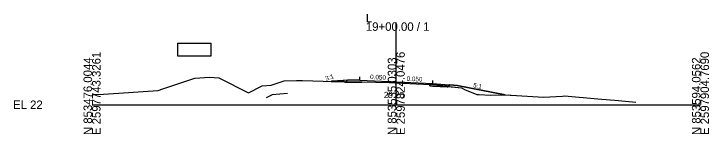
# Model space of a CAD drawing. Extents: x -26 to 1203, y -10 to 9526.
# Drawn here: x -25.7 to 202.8, y 8990.3 to 9030 of the extents above; entities that cross this region are included whole.
import ezdxf

# ---------------------------------------------------------------- set-up
doc = ezdxf.new("R2010")
doc.units = 0
for name, color, linetype in [('Default', 7, 'Continuous'), ('Exist Cross Section Cell', 7, 'Continuous'), ('Exist XS Center Line Elevation Label', 7, 'Continuous'), ('Exist XS Ground Line', 7, 'Continuous'), ('Prop XS Earthwork Shape', 7, 'Continuous'), ('Prop XS EOT Tick Mark', 7, 'Continuous'), ('Prop XS Finish Grade', 7, 'Continuous'), ('Prop XS Finish Grade Earthwork', 7, 'Continuous'), ('Prop XS Finish Grade Paved Shoulder', 7, 'Continuous'), ('Prop XS Finish Grade Pavement', 7, 'Continuous'), ('Prop XS Pvmt Edge Slope', 7, 'Continuous'), ('Prop XS SE Text', 7, 'Continuous'), ('Prop XS Side Slope Text', 7, 'Continuous'), ('Prop XS Subgrade Earthwork', 7, 'Continuous')]:
    doc.layers.add(name, color=color, linetype=linetype)

msp = doc.modelspace()

# ---------------------------------------------------------------- linework, layer by layer
at = {"layer": 'Default'}
msp.add_line((64.2, 9003.68), (59.2, 9003.27), dxfattribs=at)
msp.add_lwpolyline([(28.25, 9020.35), (39.06, 9020.35), (39.06, 9016), (28.25, 9016)], close=True, dxfattribs=at)
msp.add_lwpolyline([(59.2, 9003.27), (57.2, 9002.27)], dxfattribs=at)
at = {"layer": 'Exist Cross Section Cell'}
for p, q in [((100, 9000), (100, 9027.17)), ((0, 9000), (100, 9000)), ((100, 9000), (200, 9000))]:
    msp.add_line(p, q, dxfattribs=at)
at = {"layer": 'Exist XS Ground Line'}
for p, q in [((33.74, 9008.75), (38.63, 9009.06)), ((38.63, 9009.06), (41.64, 9008.88)), ((41.64, 9008.88), (51.45, 9003.98)), ((23.28, 9005.23), (33.74, 9008.75)), ((58.91, 9006.46), (63.16, 9007.88)), ((63.16, 9007.88), (67.16, 9008)), ((67.16, 9008), (69.16, 9007.95)), ((69.16, 9007.95), (79.41, 9007.66)), ((79.41, 9007.66), (88.8, 9007.53)), ((88.8, 9007.53), (97.62, 9007.32)), ((97.62, 9007.32), (99.87, 9007.26)), ((99.87, 9007.26), (108.97, 9006.82)), ((108.97, 9006.82), (111.07, 9006.71)), ((111.07, 9006.71), (114.42, 9006.29)), ((3.76, 9003.53), (21.77, 9004.69)), ((21.77, 9004.69), (23.28, 9005.23)), ((51.45, 9003.98), (55.91, 9006.21)), ((55.91, 9006.21), (58.91, 9006.46)), ((114.42, 9006.29), (121.48, 9005.53)), ((121.48, 9005.53), (122.67, 9004.88)), ((122.67, 9004.88), (125.12, 9003.98)), ((0, 9003.35), (1.5, 9003.41)), ((1.5, 9003.41), (3.76, 9003.53)), ((125.12, 9003.98), (126.52, 9003.34)), ((126.52, 9003.34), (127.27, 9003.35)), ((127.27, 9003.35), (130.85, 9003.19)), ((130.85, 9003.19), (136.78, 9003.25)), ((136.78, 9003.25), (137.46, 9003.21)), ((137.46, 9003.21), (137.8, 9003.2)), ((137.8, 9003.2), (148.41, 9002.47)), ((148.41, 9002.47), (154.65, 9002.88)), ((154.65, 9002.88), (155.29, 9002.96)), ((155.29, 9002.96), (166.27, 9001.98)), ((166.27, 9001.98), (173.06, 9001.35)), ((173.06, 9001.35), (178.76, 9000.89))]:
    msp.add_line(p, q, dxfattribs=at)
at = {"layer": 'Prop XS Earthwork Shape'}
for points in [[(78.58, 9007.69), (79.41, 9007.66), (82.9, 9007.61), (82.51, 9008.01), (78.76, 9007.75)], [(83.2, 9007.31), (82.9, 9007.61), (88.73, 9007.53), (88.73, 9007.33), (88, 9007.36)], [(111.03, 9006.22), (112, 9006.16), (116.84, 9005.87), (116.98, 9006.01), (114.42, 9006.29), (111.07, 9006.71), (111.03, 9006.71)], [(126.52, 9003.34), (127.27, 9003.35), (130.85, 9003.19), (135.78, 9003.24), (120, 9006.39), (117.56, 9006.59), (116.98, 9006.01), (121.48, 9005.53), (122.67, 9004.88), (125.12, 9003.98)]]:
    msp.add_lwpolyline(points, close=True, dxfattribs=at)
at = {"layer": 'Prop XS EOT Tick Mark'}
for p, q in [((88, 9008.15), (88, 9009.15)), ((112, 9006.95), (112, 9007.95))]:
    msp.add_line(p, q, dxfattribs=at)
at = {"layer": 'Prop XS Finish Grade'}
for p, q in [((84, 9008.11), (82.51, 9008.01)), ((116, 9006.71), (117.56, 9006.59))]:
    msp.add_line(p, q, dxfattribs=at)
at = {"layer": 'Prop XS Finish Grade Earthwork'}
for p, q in [((78.76, 9007.75), (78.58, 9007.69)), ((82.51, 9008.01), (78.76, 9007.75)), ((117.56, 9006.59), (120, 9006.39)), ((120, 9006.39), (135.78, 9003.24))]:
    msp.add_line(p, q, dxfattribs=at)
at = {"layer": 'Prop XS Finish Grade Paved Shoulder'}
for p, q in [((88, 9008.15), (84, 9008.11)), ((112, 9006.95), (116, 9006.71))]:
    msp.add_line(p, q, dxfattribs=at)
at = {"layer": 'Prop XS Finish Grade Pavement'}
for p, q in [((88, 9008.15), (100, 9007.55)), ((100, 9007.55), (112, 9006.95))]:
    msp.add_line(p, q, dxfattribs=at)
at = {"layer": 'Prop XS Pvmt Edge Slope'}
for p, q in [((84, 9008.11), (83.2, 9007.31)), ((116, 9006.71), (116.84, 9005.87))]:
    msp.add_line(p, q, dxfattribs=at)
at = {"layer": 'Prop XS Subgrade Earthwork'}
for p, q in [((83.2, 9007.31), (82.51, 9008.01)), ((88, 9007.36), (83.2, 9007.31)), ((88.73, 9007.33), (88, 9007.36)), ((88.73, 9007.33), (88.73, 9007.53)), ((111.03, 9006.22), (111.03, 9006.71)), ((116.84, 9005.87), (117.56, 9006.59)), ((111.03, 9006.22), (112, 9006.16)), ((112, 9006.16), (116.84, 9005.87))]:
    msp.add_line(p, q, dxfattribs=at)

# ---------------------------------------------------------------- texts
at = {"layer": 'Exist Cross Section Cell'}
for s, p in [('L', (90, 9027.17)), ('19+00.00 / 1', (90, 9024.37)), ('EL 22', (-26, 8998.6))]:
    msp.add_text(s, height=2.8, dxfattribs=at).set_placement(p)
for s, p in [('E 2597743.3261', (2.8, 8990)), ('E 2597824.0476', (102.8, 8990)), ('E 2597904.7690', (202.8, 8990)), ('N 853476.0044', (0, 8990)), ('N 853535.0303', (100, 8990)), ('N 853594.0562', (200, 8990))]:
    msp.add_text(s, height=2.8, rotation=90, dxfattribs=at).set_placement(p)
at = {"layer": 'Exist XS Center Line Elevation Label'}
msp.add_text('29.25', height=2, dxfattribs=at).set_placement((95.93, 9002.25))
at = {"layer": 'Prop XS SE Text'}
for p in [(91.38, 9008.48), (103.38, 9007.88)]:
    msp.add_text('0.050', height=1.5, rotation=357.1376, dxfattribs=at).set_placement(p)
at = {"layer": 'Prop XS Side Slope Text'}
for s, rotation, p in [('3:1', 18.4349, (76.89, 9007.87)), ('5:1', 345.9638, (125.15, 9005.82))]:
    msp.add_text(s, height=1.5, rotation=rotation, dxfattribs=at).set_placement(p)

doc.saveas('drawing.dxf')
